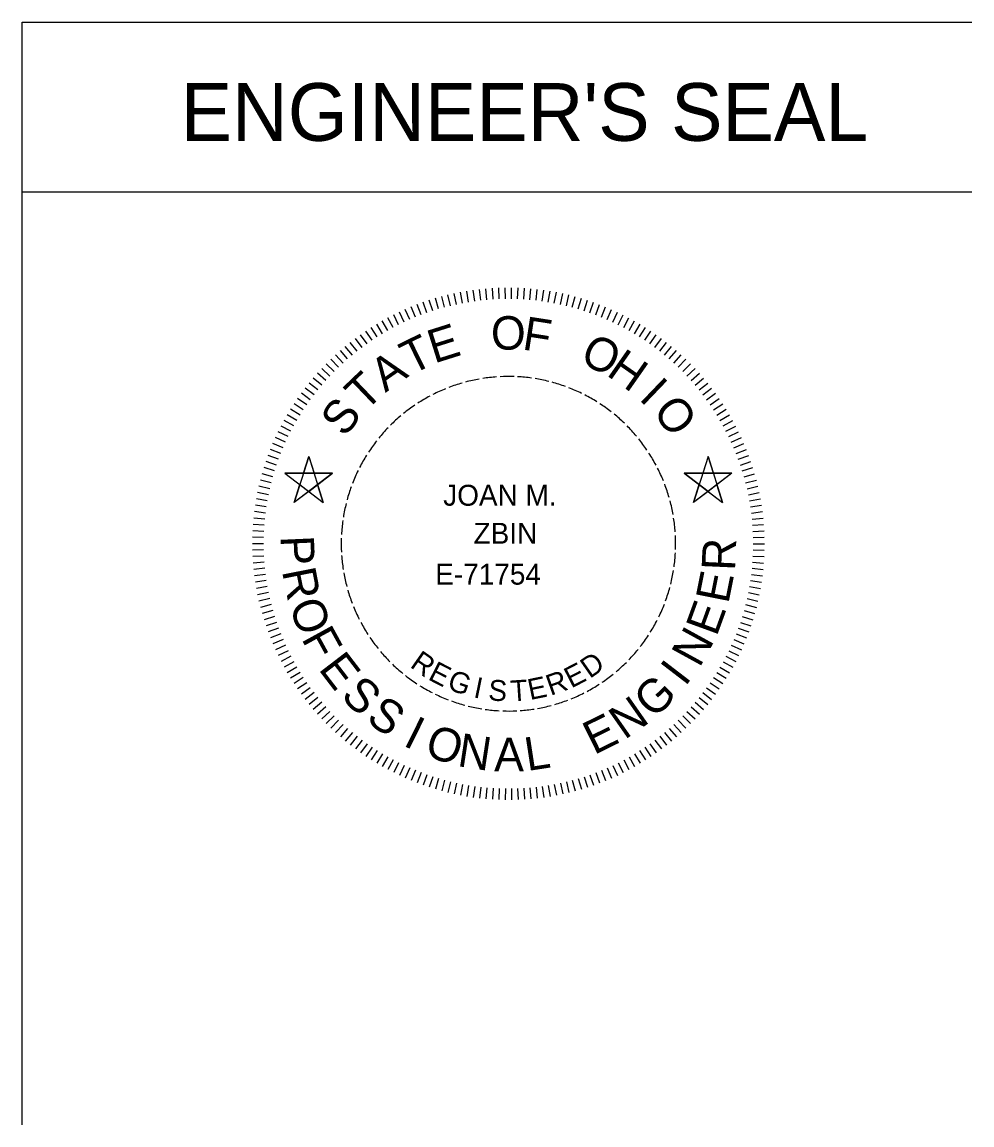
# Model space of a CAD drawing. Extents: x -6.1 to 38, y -7.7 to 22.
# Drawn here: x -5.801 to -3.001, y -6.626 to -3.376 of the extents above; entities that cross this region are included whole.
import ezdxf

# ---------------------------------------------------------------- set-up
doc = ezdxf.new("R2010")
doc.units = 0
doc.layers.add('SH_Data', color=7, linetype='Continuous')
doc.layers.add('SH_Text', color=7, linetype='Continuous')

msp = doc.modelspace()

# ---------------------------------------------------------------- linework, layer by layer
at = {"layer": 'SH_Data'}
for p, q in [((-5.8013, -6.6258), (-5.8013, -3.3758)), ((-5.8013, -3.3758), (-3.0013, -3.3758)), ((-5.8013, -3.8758), (-3.0013, -3.8758))]:
    msp.add_line(p, q, dxfattribs=at)
at = {"layer": 'SH_Text'}
for p, q in [((-4.3948, -4.1917), (-4.396, -4.1591)), ((-4.3767, -4.1913), (-4.3771, -4.1586)), ((-4.3585, -4.1913), (-4.3581, -4.1586)), ((-4.3404, -4.1917), (-4.3392, -4.1591)), ((-4.5733, -4.2212), (-4.5827, -4.1899)), ((-4.5559, -4.2162), (-4.5644, -4.1847)), ((-4.5383, -4.2117), (-4.546, -4.18)), ((-4.5206, -4.2076), (-4.5276, -4.1757)), ((-4.5029, -4.204), (-4.509, -4.1719)), ((-4.485, -4.2008), (-4.4903, -4.1686)), ((-4.4671, -4.1981), (-4.4716, -4.1658)), ((-4.4491, -4.1958), (-4.4528, -4.1634)), ((-4.431, -4.194), (-4.4339, -4.1615)), ((-4.4129, -4.1927), (-4.415, -4.1601)), ((-4.3223, -4.1927), (-4.3202, -4.1601)), ((-4.3042, -4.194), (-4.3013, -4.1615)), ((-4.2861, -4.1958), (-4.2825, -4.1634)), ((-4.2681, -4.1981), (-4.2636, -4.1658)), ((-4.2502, -4.2008), (-4.2449, -4.1686)), ((-4.2324, -4.204), (-4.2262, -4.1719)), ((-4.2146, -4.2076), (-4.2077, -4.1757)), ((-4.1969, -4.2117), (-4.1892, -4.18)), ((-4.1793, -4.2162), (-4.1708, -4.1847)), ((-4.1619, -4.2212), (-4.1526, -4.1899)), ((-4.6584, -4.2524), (-4.6716, -4.2225)), ((-4.6417, -4.2453), (-4.6541, -4.2151)), ((-4.6249, -4.2386), (-4.6365, -4.2081)), ((-4.6079, -4.2324), (-4.6187, -4.2016)), ((-4.5907, -4.2266), (-4.6008, -4.1955)), ((-4.1446, -4.2266), (-4.1345, -4.1955)), ((-4.1274, -4.2324), (-4.1165, -4.2016)), ((-4.1103, -4.2386), (-4.0987, -4.2081)), ((-4.0935, -4.2453), (-4.0811, -4.2151)), ((-4.0768, -4.2524), (-4.0636, -4.2225)), ((-4.7233, -4.2849), (-4.7394, -4.2565)), ((-4.7074, -4.2762), (-4.7227, -4.2474)), ((-4.6913, -4.2679), (-4.7059, -4.2387)), ((-4.675, -4.2599), (-4.6889, -4.2304)), ((-4.0603, -4.2599), (-4.0464, -4.2304)), ((-4.044, -4.2679), (-4.0293, -4.2387)), ((-4.0278, -4.2762), (-4.0125, -4.2474)), ((-4.0119, -4.2849), (-3.9959, -4.2565)), ((-4.7696, -4.3135), (-4.7878, -4.2864)), ((-4.7544, -4.3036), (-4.7719, -4.276)), ((-4.739, -4.2941), (-4.7557, -4.2661)), ((-3.9963, -4.2941), (-3.9795, -4.2661)), ((-3.9808, -4.3036), (-3.9633, -4.276)), ((-3.9656, -4.3135), (-3.9475, -4.2864)), ((-4.8136, -4.3455), (-4.8338, -4.3198)), ((-4.7992, -4.3345), (-4.8187, -4.3083)), ((-4.7845, -4.3238), (-4.8034, -4.2971)), ((-3.9507, -4.3238), (-3.9318, -4.2971)), ((-3.936, -4.3345), (-3.9165, -4.3083)), ((-3.9216, -4.3455), (-3.9014, -4.3198)), ((-4.8416, -4.3686), (-4.863, -4.344)), ((-4.8277, -4.3569), (-4.8485, -4.3317)), ((-3.9075, -4.3569), (-3.8867, -4.3317)), ((-3.8937, -4.3686), (-3.8722, -4.344)), ((-4.8812, -4.4059), (-4.9045, -4.3829)), ((-4.8683, -4.3931), (-4.891, -4.3696)), ((-4.8551, -4.3807), (-4.8771, -4.3566)), ((-3.8801, -4.3807), (-3.8581, -4.3566)), ((-3.8669, -4.3931), (-3.8443, -4.3696)), ((-3.854, -4.4059), (-3.8308, -4.3829)), ((-4.9061, -4.4323), (-4.9304, -4.4106)), ((-4.8938, -4.4189), (-4.9176, -4.3966)), ((-3.8414, -4.4189), (-3.8176, -4.3966)), ((-3.8292, -4.4323), (-3.8048, -4.4106)), ((-4.9295, -4.46), (-4.9549, -4.4395)), ((-4.918, -4.446), (-4.9429, -4.4249)), ((-3.8173, -4.446), (-3.7924, -4.4249)), ((-3.8057, -4.46), (-3.7803, -4.4395)), ((-4.9516, -4.4888), (-4.978, -4.4696)), ((-4.9407, -4.4742), (-4.9667, -4.4544)), ((-3.7945, -4.4742), (-3.7686, -4.4544)), ((-3.7836, -4.4888), (-3.7572, -4.4696)), ((-4.9819, -4.534), (-5.0097, -4.5168)), ((-4.9722, -4.5187), (-4.9995, -4.5008)), ((-4.9621, -4.5036), (-4.989, -4.4851)), ((-3.7732, -4.5036), (-3.7463, -4.4851)), ((-3.7631, -4.5187), (-3.7357, -4.5008)), ((-3.7533, -4.534), (-3.7255, -4.5168)), ((-5.0002, -4.5653), (-5.0288, -4.5496)), ((-4.9912, -4.5495), (-5.0194, -4.5331)), ((-3.744, -4.5495), (-3.7158, -4.5331)), ((-3.7351, -4.5653), (-3.7064, -4.5496)), ((-5.0087, -4.5813), (-5.0377, -4.5663)), ((-3.7265, -4.5813), (-3.6975, -4.5663)), ((-5.0246, -4.614), (-5.0543, -4.6004)), ((-5.0168, -4.5975), (-5.0462, -4.5833)), ((-3.7184, -4.5975), (-3.689, -4.5833)), ((-3.7107, -4.614), (-3.6809, -4.6004)), ((-5.0388, -4.6473), (-5.0691, -4.6353)), ((-5.0319, -4.6306), (-5.0619, -4.6178)), ((-3.7034, -4.6306), (-3.6733, -4.6178)), ((-3.6965, -4.6473), (-3.6661, -4.6353)), ((-5.0513, -4.6814), (-5.0822, -4.6709)), ((-5.0452, -4.6643), (-5.0759, -4.653)), ((-4.9561, -4.656), (-4.9989, -4.7918)), ((-4.9561, -4.656), (-4.9133, -4.7918)), ((-3.7791, -4.656), (-3.8219, -4.7918)), ((-3.7791, -4.656), (-3.7363, -4.7918)), ((-3.69, -4.6643), (-3.6593, -4.653)), ((-3.684, -4.6814), (-3.653, -4.6709)), ((-5.062, -4.716), (-5.0934, -4.7071)), ((-5.0569, -4.6986), (-5.088, -4.6889)), ((-5.0263, -4.7051), (-4.886, -4.7051)), ((-5.0263, -4.7051), (-4.9133, -4.7918)), ((-4.886, -4.7051), (-4.9989, -4.7918)), ((-3.8493, -4.7051), (-3.7363, -4.7918)), ((-3.709, -4.7051), (-3.8493, -4.7051)), ((-3.709, -4.7051), (-3.8219, -4.7918)), ((-3.6784, -4.6986), (-3.6472, -4.6889)), ((-3.6732, -4.716), (-3.6418, -4.7071)), ((-5.0711, -4.7512), (-5.1029, -4.7439)), ((-5.0668, -4.7335), (-5.0984, -4.7254)), ((-3.6685, -4.7335), (-3.6368, -4.7254)), ((-3.6642, -4.7512), (-3.6323, -4.7439)), ((-5.0749, -4.7689), (-5.1069, -4.7624)), ((-3.6603, -4.7689), (-3.6283, -4.7624)), ((-5.0813, -4.8046), (-5.1135, -4.7997)), ((-5.0783, -4.7867), (-5.1104, -4.781)), ((-3.6569, -4.7867), (-3.6248, -4.781)), ((-3.654, -4.8046), (-3.6217, -4.7997)), ((-5.0858, -4.8406), (-5.1183, -4.8373)), ((-5.0838, -4.8226), (-5.1161, -4.8185)), ((-3.6515, -4.8226), (-3.6191, -4.8185)), ((-3.6494, -4.8406), (-3.6169, -4.8373)), ((-5.0874, -4.8587), (-5.12, -4.8562)), ((-3.6478, -4.8587), (-3.6153, -4.8562)), ((-5.0892, -4.8949), (-5.1219, -4.8941)), ((-5.0885, -4.8768), (-5.1211, -4.8752)), ((-3.6467, -4.8768), (-3.6141, -4.8752)), ((-3.646, -4.8949), (-3.6134, -4.8941)), ((-5.0894, -4.9131), (-5.1221, -4.9131)), ((-5.0892, -4.9312), (-5.1219, -4.932)), ((-3.646, -4.9312), (-3.6134, -4.932)), ((-3.6458, -4.9131), (-3.6131, -4.9131)), ((-5.0885, -4.9493), (-5.1211, -4.951)), ((-5.0874, -4.9674), (-5.12, -4.9699)), ((-3.6478, -4.9674), (-3.6153, -4.9699)), ((-3.6467, -4.9493), (-3.6141, -4.951)), ((-5.0858, -4.9855), (-5.1183, -4.9888)), ((-5.0838, -5.0035), (-5.1161, -5.0076)), ((-3.6515, -5.0035), (-3.6191, -5.0076)), ((-3.6494, -4.9855), (-3.6169, -4.9888)), ((-5.0813, -5.0215), (-5.1135, -5.0264)), ((-3.654, -5.0215), (-3.6217, -5.0264)), ((-5.0783, -5.0394), (-5.1104, -5.0451)), ((-5.0749, -5.0572), (-5.1069, -5.0637)), ((-3.6603, -5.0572), (-3.6283, -5.0637)), ((-3.6569, -5.0394), (-3.6248, -5.0451)), ((-5.0711, -5.0749), (-5.1029, -5.0823)), ((-5.0668, -5.0926), (-5.0984, -5.1007)), ((-3.6685, -5.0926), (-3.6368, -5.1007)), ((-3.6642, -5.0749), (-3.6323, -5.0823)), ((-5.062, -5.1101), (-5.0934, -5.119)), ((-5.0569, -5.1275), (-5.088, -5.1372)), ((-3.6784, -5.1275), (-3.6472, -5.1372)), ((-3.6732, -5.1101), (-3.6418, -5.119)), ((-5.0513, -5.1447), (-5.0822, -5.1552)), ((-5.0452, -5.1618), (-5.0759, -5.1731)), ((-3.69, -5.1618), (-3.6593, -5.1731)), ((-3.684, -5.1447), (-3.653, -5.1552)), ((-5.0388, -5.1788), (-5.0691, -5.1908)), ((-5.0319, -5.1956), (-5.0619, -5.2083)), ((-3.7034, -5.1956), (-3.6733, -5.2083)), ((-3.6965, -5.1788), (-3.6661, -5.1908)), ((-5.0246, -5.2122), (-5.0543, -5.2257)), ((-5.0168, -5.2286), (-5.0462, -5.2429)), ((-3.7184, -5.2286), (-3.689, -5.2429)), ((-3.7107, -5.2122), (-3.6809, -5.2257)), ((-5.0087, -5.2448), (-5.0377, -5.2598)), ((-5.0002, -5.2608), (-5.0288, -5.2765)), ((-3.7351, -5.2608), (-3.7064, -5.2765)), ((-3.7265, -5.2448), (-3.6975, -5.2598)), ((-4.9912, -5.2766), (-5.0194, -5.293)), ((-4.9819, -5.2922), (-5.0097, -5.3093)), ((-3.7533, -5.2922), (-3.7255, -5.3093)), ((-3.744, -5.2766), (-3.7158, -5.293)), ((-4.9722, -5.3075), (-4.9995, -5.3253)), ((-4.9621, -5.3225), (-4.989, -5.3411)), ((-3.7732, -5.3225), (-3.7463, -5.3411)), ((-3.7631, -5.3075), (-3.7357, -5.3253)), ((-4.9516, -5.3373), (-4.978, -5.3565)), ((-4.9407, -5.3519), (-4.9667, -5.3717)), ((-3.7945, -5.3519), (-3.7686, -5.3717)), ((-3.7836, -5.3373), (-3.7572, -5.3565)), ((-4.9295, -5.3662), (-4.9549, -5.3866)), ((-4.918, -5.3801), (-4.9429, -5.4013)), ((-4.9061, -5.3938), (-4.9304, -5.4156)), ((-3.8292, -5.3938), (-3.8048, -5.4156)), ((-3.8173, -5.3801), (-3.7924, -5.4013)), ((-3.8057, -5.3662), (-3.7803, -5.3866)), ((-4.8938, -5.4072), (-4.9176, -5.4295)), ((-4.8812, -5.4203), (-4.9045, -5.4432)), ((-3.854, -5.4203), (-3.8308, -5.4432)), ((-3.8414, -5.4072), (-3.8176, -5.4295)), ((-4.8683, -5.433), (-4.891, -5.4565)), ((-4.8551, -5.4454), (-4.8771, -5.4695)), ((-4.8416, -5.4575), (-4.863, -5.4821)), ((-3.8937, -5.4575), (-3.8722, -5.4821)), ((-3.8801, -5.4454), (-3.8581, -5.4695)), ((-3.8669, -5.433), (-3.8443, -5.4565)), ((-4.8277, -5.4692), (-4.8485, -5.4944)), ((-4.8136, -5.4806), (-4.8338, -5.5063)), ((-4.7992, -5.4917), (-4.8187, -5.5178)), ((-3.936, -5.4917), (-3.9165, -5.5178)), ((-3.9216, -5.4806), (-3.9014, -5.5063)), ((-3.9075, -5.4692), (-3.8867, -5.4944)), ((-4.7845, -5.5023), (-4.8034, -5.529)), ((-4.7696, -5.5126), (-4.7878, -5.5397)), ((-4.7544, -5.5225), (-4.7719, -5.5501)), ((-3.9808, -5.5225), (-3.9633, -5.5501)), ((-3.9656, -5.5126), (-3.9475, -5.5397)), ((-3.9507, -5.5023), (-3.9318, -5.529)), ((-4.739, -5.5321), (-4.7557, -5.5601)), ((-4.7233, -5.5412), (-4.7394, -5.5696)), ((-4.7074, -5.5499), (-4.7227, -5.5787)), ((-4.0278, -5.5499), (-4.0125, -5.5787)), ((-4.0119, -5.5412), (-3.9959, -5.5696)), ((-3.9963, -5.5321), (-3.9795, -5.5601)), ((-4.6913, -5.5583), (-4.7059, -5.5875)), ((-4.675, -5.5662), (-4.6889, -5.5957)), ((-4.6584, -5.5737), (-4.6716, -5.6036)), ((-4.6417, -5.5808), (-4.6541, -5.611)), ((-4.6249, -5.5875), (-4.6365, -5.618)), ((-4.1103, -5.5875), (-4.0987, -5.618)), ((-4.0935, -5.5808), (-4.0811, -5.611)), ((-4.0768, -5.5737), (-4.0636, -5.6036)), ((-4.0603, -5.5662), (-4.0464, -5.5957)), ((-4.044, -5.5583), (-4.0293, -5.5875)), ((-4.6079, -5.5937), (-4.6187, -5.6245)), ((-4.5907, -5.5996), (-4.6008, -5.6306)), ((-4.5733, -5.605), (-4.5827, -5.6363)), ((-4.5559, -5.6099), (-4.5644, -5.6414)), ((-4.5383, -5.6144), (-4.546, -5.6461)), ((-4.5206, -5.6185), (-4.5276, -5.6504)), ((-4.5029, -5.6221), (-4.509, -5.6542)), ((-4.2324, -5.6221), (-4.2262, -5.6542)), ((-4.2146, -5.6185), (-4.2077, -5.6504)), ((-4.1969, -5.6144), (-4.1892, -5.6461)), ((-4.1793, -5.6099), (-4.1708, -5.6414)), ((-4.1619, -5.605), (-4.1526, -5.6363)), ((-4.1446, -5.5996), (-4.1345, -5.6306)), ((-4.1274, -5.5937), (-4.1165, -5.6245)), ((-4.485, -5.6253), (-4.4903, -5.6575)), ((-4.4671, -5.628), (-4.4716, -5.6604)), ((-4.4491, -5.6303), (-4.4528, -5.6627)), ((-4.431, -5.6321), (-4.4339, -5.6646)), ((-4.4129, -5.6335), (-4.415, -5.6661)), ((-4.3948, -5.6344), (-4.396, -5.667)), ((-4.3767, -5.6348), (-4.3771, -5.6675)), ((-4.3585, -5.6348), (-4.3581, -5.6675)), ((-4.3404, -5.6344), (-4.3392, -5.667)), ((-4.3223, -5.6335), (-4.3202, -5.6661)), ((-4.3042, -5.6321), (-4.3013, -5.6646)), ((-4.2861, -5.6303), (-4.2825, -5.6627)), ((-4.2681, -5.628), (-4.2636, -5.6604)), ((-4.2502, -5.6253), (-4.2449, -5.6575))]:
    msp.add_line(p, q, dxfattribs=at)
for points in [[(-4.9561, -4.656), (-4.9406, -4.7051), (-4.9716, -4.7051)], [(-3.7791, -4.656), (-3.7946, -4.7051), (-3.7636, -4.7051)], [(-4.886, -4.7051), (-5.0263, -4.7051), (-4.9561, -4.7589)], [(-3.8493, -4.7051), (-3.709, -4.7051), (-3.7791, -4.7589)], [(-4.9822, -4.7388), (-4.9561, -4.7589), (-4.9989, -4.7918)], [(-4.93, -4.7388), (-4.9561, -4.7589), (-4.9133, -4.7918)], [(-3.8053, -4.7388), (-3.7791, -4.7589), (-3.8219, -4.7918)], [(-3.753, -4.7388), (-3.7791, -4.7589), (-3.7363, -4.7918)]]:
    msp.add_lwpolyline(points, close=True, dxfattribs=at)
for start, end in [(106.0561, 110.8364), (100.0561, 104.8364), (94.0561, 98.8364), (88.0561, 92.8364), (82.0561, 86.8364), (76.0561, 80.8364), (70.0561, 74.8364), (118.0561, 122.8364), (112.0561, 116.8364), (64.0561, 68.8364), (58.0561, 62.8364), (124.0561, 128.8364), (52.0561, 56.8364), (130.0561, 134.8364), (46.0561, 50.8364), (136.0561, 140.8364), (40.0561, 44.8364), (142.0561, 146.8364), (34.0561, 38.8364), (28.0561, 32.8364), (148.0561, 152.8364), (154.0561, 158.8364), (22.0561, 26.8364), (160.0561, 164.8364), (16.0561, 20.8364), (166.0561, 170.8364), (10.0561, 14.8364), (4.0561, 8.8364), (172.0561, 176.8364), (178.0561, 182.8364), (358.0561, 2.8364), (184.0561, 188.8364), (352.0561, 356.8364), (190.0561, 194.8364), (346.0561, 350.8364), (196.0561, 200.8364), (340.0561, 344.8364), (202.0561, 206.8364), (334.0561, 338.8364), (208.0561, 212.8364), (328.0561, 332.8364), (214.0561, 218.8364), (322.0561, 326.8364), (220.0561, 224.8364), (316.0561, 320.8364), (310.0561, 314.8364), (226.0561, 230.8364), (304.0561, 308.8364), (232.0561, 236.8364), (298.0561, 302.8364), (238.0561, 242.8364), (244.0561, 248.8364), (292.0561, 296.8364), (250.0561, 254.8364), (256.0561, 260.8364), (280.0561, 284.8364), (286.0561, 290.8364), (262.0561, 266.8364), (268.0561, 272.8364), (274.0561, 278.8364)]:
    msp.add_arc((-4.3676, -4.9131), 0.4929, start, end, dxfattribs=at)

# ---------------------------------------------------------------- texts
for s, height, p in [("ENGINEER'S SEAL", 0.17, (-5.3338, -3.7258)), ('O', 0.0986, (-4.4192, -4.3411)), ('JOAN M.', 0.06161, (-4.5598, -4.801)), ('ZBIN', 0.06161, (-4.4703, -4.9131)), ('E-71754', 0.06161, (-4.5833, -5.0336)), ('A', 0.0986, (-4.4099, -5.5836))]:
    msp.add_text(s, height=height, dxfattribs=at).set_placement(p)
for s, height, rotation, p in [('F', 0.0986, 351.25, (-4.3293, -4.3402)), ('E', 0.0986, 17.5, (-4.5866, -4.3824)), ('T', 0.0986, 26.25, (-4.6543, -4.4167)), ('O', 0.0986, 333.75, (-4.1609, -4.3772)), ('H', 0.0986, 325, (-4.0818, -4.4149)), ('A', 0.0986, 35, (-4.7303, -4.4688)), ('T', 0.0986, 43.75, (-4.7903, -4.5259)), ('I', 0.0986, 316.25, (-3.9856, -4.4869)), ('O', 0.0986, 307.5, (-3.9453, -4.5239)), ('S', 0.0986, 52.5, (-4.85, -4.6021)), ('P', 0.0986, 272.5, (-5.0398, -4.8907)), ('R', 0.0986, 87.5, (-3.6999, -4.9939)), ('R', 0.0986, 281.25, (-5.0354, -4.9932)), ('E', 0.0986, 78.75, (-3.7196, -5.0922)), ('O', 0.0986, 290, (-5.0154, -5.0939)), ('E', 0.0986, 70, (-3.7544, -5.1887)), ('F', 0.0986, 298.75, (-4.9792, -5.1924)), ('N', 0.0986, 61.25, (-3.8046, -5.2809)), ('E', 0.0986, 307.5, (-4.9296, -5.2822)), ('R', 0.0616, 325, (-4.6604, -5.2749)), ('E', 0.0616, 332.7778, (-4.6074, -5.3118)), ('E', 0.0616, 27.2222, (-4.1826, -5.34)), ('D', 0.0616, 35, (-4.1277, -5.3119)), ('I', 0.0986, 52.5, (-3.8471, -5.3362)), ('G', 0.0616, 340.5556, (-4.5512, -5.3406)), ('R', 0.0616, 19.4444, (-4.2435, -5.3616)), ('S', 0.0986, 316.25, (-4.8652, -5.365)), ('I', 0.0616, 348.3333, (-4.473, -5.3654)), ('S', 0.0616, 356.1111, (-4.4284, -5.3743)), ('T', 0.0616, 3.8889, (-4.3595, -5.3779)), ('E', 0.0616, 11.6667, (-4.3039, -5.374)), ('G', 0.0986, 43.75, (-3.9395, -5.4315)), ('S', 0.0986, 325, (-4.7907, -5.4354)), ('N', 0.0986, 35, (-4.0253, -5.492)), ('I', 0.0986, 333.75, (-4.681, -5.5062)), ('E', 0.0986, 26.25, (-4.1152, -5.5363)), ('O', 0.0986, 342.5, (-4.6185, -5.5371)), ('N', 0.0986, 351.25, (-4.5207, -5.568)), ('L', 0.0986, 8.75, (-4.312, -5.583))]:
    msp.add_text(s, height=height, rotation=rotation, dxfattribs=at).set_placement(p)

doc.saveas('drawing.dxf')
